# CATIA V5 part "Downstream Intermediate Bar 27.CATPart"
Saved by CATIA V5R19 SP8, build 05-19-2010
Part number: Downstream Intermediate Bar 27
Bounding box of the stored display mesh (mm): x -11 to 11, y 990 to 1110, z 440.077 to 509.923
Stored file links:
  G:\EU_thinkMotion\CFAO_2010\MMS_groupe3\MMS_groupe3\A reprendre\fovide\fovide\Downstream Intermediate Bar 27.CATPart
  G:\EU_thinkMotion\CFAO_2010\MMS_groupe3\MMS_groupe3\A reprendre\fovide\fovide\fovide.CATProduct
  G:\EU_thinkMotion\CFAO_2010\MMS_groupe3\MMS_groupe3\A reprendre\fovide\fovide\SQLT Downstream Intermediate Bar.CATPart
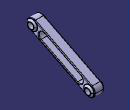
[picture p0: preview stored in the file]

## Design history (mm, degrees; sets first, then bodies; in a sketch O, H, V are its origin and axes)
Set1
  Plane1: linked copy from another document
  Point1 "Point.D": linked copy from another document
  Line1: linked copy from another document
  Point2 "Point.E": linked copy from another document
  Plane2: linked copy from another document
  Line2: linked copy from another document
  Line3: linked copy from another document
Body1 (main body)
  Sketch1 on Plane1, origin (0, 0, 0), H (0, 1, 0), V (0, 0, 1)
    line L1 (995.5279, 491.0557) -> (1004.4721, 508.9443)
    point P2 (1004.4721, 508.9443)
    line L2 (1004.4721, 508.9443) -> (1104.4721, 458.9443)
    point P3 (1004.4721, 508.9443)
    line L3 (995.5279, 491.0557) -> (1095.5279, 441.0557)
    line L4 (1104.4721, 458.9443) -> (1095.5279, 441.0557)
    reference projected line E1 (1000, 500) -> (1100, 450) from Line1
    reference projected line E2 (1000, 500) -> (1100, 450) from Line1
    reference projected point E3 (1000, 500) from Point1
    reference projected point E4 (1100, 450) from Point2
    length L4 = 20
    distance L2 E2 = 10
    coincidence: P3 L1, P3 P2, L1 E3, L4 E4
    perpendicularity: L4 L2
    parallelism: L3 L2, L1 L4, L3 E1
  Pad1: profile Sketch1, direction (1, 0, 0), length 8, mirrored extent
  Sketch2 on Plane1, origin (0, 0, 0), H (0, 1, 0), V (0, 0, 1)
    circle A1 centre (1000, 500) radius 10
    point P1 (1000, 500)
    reference projected point E1 (1000, 500) from Point1
    circle A2 centre (1100, 450) radius 10
    point P2 (1100, 450)
    reference projected point E2 (1100, 450) from Point2
    radius A1 = 10
    radius A2 = 10
    coincidence: P1 E1, P2 E2
  Pad2: profile Sketch2, direction (1, 0, 0), length 8, mirrored extent
  Sketch3 on Plane2, origin (0, 400, 800), H (-1, 0, 0), V (0, -0.8944, 0.4472)
    line L1 (-8, -661.8204) -> (-8, -670.8204)
    point P1 (-8, -661.8204)
    line L2 (-8, -670.8204) -> (-11, -670.8204)
    line L3 (-11, -670.8204) -> (-11, -664.8204)
    point P4 (-11, -664.8204)
    arc A1 centre (-1.8678, -670.9526) radius 11 from (-8, -661.8204) to (-11, -664.8204) ccw
    point P6 (-8, -661.8204)
    point P7 (-11, -664.8204)
    reference projected line E1 (150, -670.8204) -> (-150, -670.8204) from Line2
    reference projected line E2 (-8, -675.8204) -> (-8, -665.8204) from edge [face of Pad2 from Sketch2.A1 | face of Pad2]
    line L4 (8, -661.8204) -> (8, -670.8204)
    point P8 (8, -661.8204)
    line L5 (8, -670.8204) -> (11, -670.8204)
    point P10 (11, -670.8204)
    line L6 (11, -670.8204) -> (11, -664.8204)
    point P11 (11, -670.8204)
    point P12 (11, -664.8204)
    arc A2 centre (1.8678, -670.9526) radius 11 from (11, -664.8204) to (8, -661.8204) ccw
    point P13 (1.8678, -670.9526)
    point P14 (11, -664.8204)
    point P15 (8, -661.8204)
    reference projected line E3 (8, -680.8204) -> (8, -660.8204) from edge [face of Pad2 | face of Pad2 from Sketch2.A1]
    reference projected line E4 (150, -670.8204) -> (-150, -670.8204) from Line2
    length L1 = 9
    length L3 = 6
    length L2 = 3
    length L4 = 9
    length L6 = 6
    length L5 = 3
    distance P13 A2 = 11
    radius A1 = 11
    vertical: L1 V, L3 V, L4 V, L6 V
    horizontal: L2 H, L5 H
    coincidence: P6 P1, P7 P4, L2 E1, L1 E2, P11 L5, P15 P8, P14 P12, L4 E3, P10 P11, L5 E4
  Shaft1: profile Sketch3, axis Line2, angle 360
  Sketch4 on face of Shaft1 from Sketch3.L3, origin (11, 1000, 500), H (0, 1, 0), V (0, 0, 1)
    point P1 (0, 0)
    intersected point E1 (0, 0) from Line2
    coincidence: E1 P1
  Hole1: placed by Sketch4, at (11, 1000, 500) direction (-1, 0, 0), diameter 10, through (limit type 3)
  Sketch5 on Plane2, origin (0, 400, 800), H (-1, 0, 0), V (0, -0.8944, 0.4472)
    point P1 (-11, -776.6238)
    point P2 (-8, -773.6238)
    arc A1 centre (-1.8678, -782.756) radius 11 from (-8, -773.6238) to (-11, -776.6238) ccw
    point P4 (-11, -776.6238)
    line L1 (-11, -782.6238) -> (-11, -776.6238)
    line L2 (-8, -782.6238) -> (-11, -782.6238)
    point P7 (-8, -773.6238)
    line L3 (-8, -773.6238) -> (-8, -782.6238)
    point P8 (8, -773.6238)
    point P9 (11, -776.6238)
    point P10 (1.8678, -782.756)
    arc A2 centre (1.8678, -782.756) radius 11 from (11, -776.6238) to (8, -773.6238) ccw
    point P12 (8, -773.6238)
    line L4 (8, -773.6238) -> (8, -782.6238)
    point P13 (11, -782.6238)
    line L5 (8, -782.6238) -> (11, -782.6238)
    point P14 (11, -776.6238)
    point P15 (11, -782.6238)
    line L6 (11, -782.6238) -> (11, -776.6238)
    reference projected line E1 (150, -782.6238) -> (-150, -782.6238) from Line3
    reference projected line E2 (150, -782.6238) -> (-150, -782.6238) from Line3
    reference projected line E3 (-8, -782.6238) -> (-8, -670.8204) from edge [face of Pad1 from Sketch1.L2 | face of Pad2]
    reference projected line E4 (8, -782.6238) -> (8, -670.8204) from edge [face of Pad2 | face of Pad1 from Sketch1.L2]
    distance P10 A2 = 11
    length L6 = 6
    length L4 = 9
    length L5 = 3
    length L3 = 9
    length L1 = 6
    radius A1 = 11
    length L2 = 3
    horizontal: L5 H, L2 H
    vertical: L6 V, L4 V, L1 V, L3 V
    coincidence: L5 E1, P15 P13, P14 P9, P8 P12, L2 E2, P1 P4, P7 P2, L3 E3, L4 E4
  Shaft2: profile Sketch5, axis Line3, angle 360
  Sketch6 on face of Shaft2 from Sketch5.L1, origin (11, 1100, 450), H (0, 1, 0), V (0, 0, 1)
    point P1 (0, 0)
    intersected point E1 (0, 0) from Line3
    coincidence: E1 P1
  Hole2: placed by Sketch6, at (11, 1100, 450) direction (-1, 0, 0), diameter 10, through (limit type 3)
  Sketch7 on face of Pad2, origin (8, 0, 0), H (0, 1, 0), V (0, 0, 1)
    arc A1 centre (1017.8885, 491.0557) radius 7.002 from (1021.1669, 497.2428) to (1014.6098, 484.8689) ccw
    point P1 (1017.8885, 491.0557)
    line L1 (1021.1669, 497.2428) -> (1085.242, 465.2053)
    arc A2 centre (1082.1115, 458.9443) radius 7 from (1085.242, 465.2053) to (1078.9818, 452.6829) cw
    point P5 (1082.1115, 458.9443)
    line L2 (1078.9818, 452.6829) -> (1014.6098, 484.8689)
    reference projected point E1 (1000, 500) from Point1
    reference projected point E2 (1100, 450) from Point2
    reference projected line E3 (1000, 500) -> (1100, 450) from Line1
    reference projected line E4 (1000, 500) -> (1100, 450) from Line1
    reference projected line E5 (1000, 500) -> (1100, 450) from Line1
    distance P1 E1 = 20
    distance P5 E2 = 20
    distance L1 L2 = 14
    distance L1 E5 = 7
    tangency: A2 L1
    parallelism: L1 E3, L2 E4
  Pocket1: profile Sketch7, direction (-1, 0, 0), through (limit type 3)
  Fillet1: radius 1, on face of Pad2 (x2)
